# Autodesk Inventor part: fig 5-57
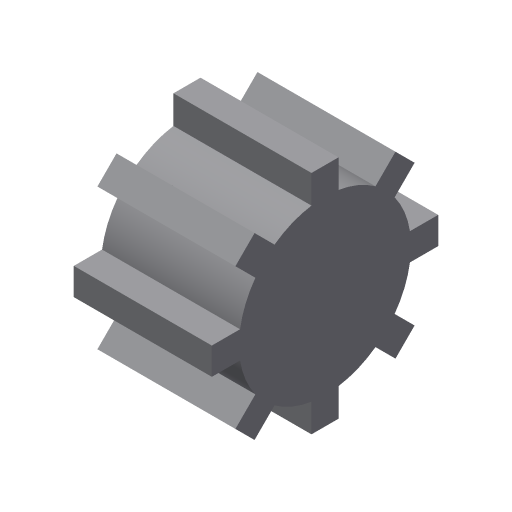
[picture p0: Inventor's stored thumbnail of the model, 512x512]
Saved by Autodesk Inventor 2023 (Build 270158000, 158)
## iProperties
Created: 2005-12
Part Number: fig 5-57
Document SubType Name: Modeling
Designer: CADCIM
Density: 1 g/cm^3
Material: Generic
Appearance: Default
Author: CADCIM
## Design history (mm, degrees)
sketch "Sketch1"
  geometry: C1 r 27.506 at (0, 0)
  constraints: 1 centre point
extrude "Extrusion1" new body sketch "Sketch1" distance "d0" = 20; taper "d1" = 0 deg
sketch "Sketch2"
  geometry: L1 (-12.302, -1.705)-(-16.396, -1.705); L2 (-16.396, -1.705)-(-16.396, 2.216); L3 (-16.396, 2.216)-(-12.302, 2.216); L4 (-7.311, -9.833)-(-10.206, -12.728); L5 (-10.206, -12.728)-(-12.979, -9.955); L6 (-12.979, -9.955)-(-10.084, -7.06); L7 (1.966, -12.051)-(1.966, -16.145); L8 (1.966, -16.145)-(-1.956, -16.145); L9 (-1.956, -16.145)-(-1.956, -12.051); L10 (10.093, -7.06)-(12.988, -9.955); L11 (12.988, -9.955)-(10.215, -12.728); L12 (10.215, -12.728)-(7.32, -9.833); L13 (12.311, 2.216)-(16.405, 2.216); L14 (16.405, 2.216)-(16.405, -1.705); L15 (16.405, -1.705)-(12.311, -1.705); L16 (7.32, 10.344)-(10.215, 13.239); L17 (10.215, 13.239)-(12.988, 10.466); L18 (12.988, 10.466)-(10.093, 7.571); L19 (-1.956, 12.562)-(-1.956, 16.656); L20 (-1.956, 16.656)-(1.966, 16.656); L21 (1.966, 16.656)-(1.966, 12.562); L22 (-10.084, 7.571)-(-12.979, 10.466); L23 (-12.979, 10.466)-(-10.206, 13.239); L24 (-10.206, 13.239)-(-7.311, 10.344); A1 r 12.462 centre (0.005, 0.256) between (-12.302, -1.705) and (-10.084, -7.06); A2 r 12.462 centre (0.005, 0.256) between (-7.311, -9.833) and (-1.956, -12.051); A3 r 12.462 centre (0.005, 0.256) between (1.966, -12.051) and (7.32, -9.833); A4 r 12.462 centre (0.005, 0.256) between (10.093, -7.06) and (12.311, -1.705); A5 r 12.462 centre (0.005, 0.256) between (12.311, 2.216) and (10.093, 7.571); A6 r 12.462 centre (0.005, 0.256) between (7.32, 10.344) and (1.966, 12.562); A7 r 12.462 centre (0.005, 0.256) between (-1.956, 12.562) and (-7.311, 10.344); A8 r 12.462 centre (0.005, 0.256) between (-10.084, 7.571) and (-12.302, 2.216)
  constraints: 48 end point, 16 point on circle, 8 centre point, 2 parallel, 1 horizontal, 1 perpendicular, 57 other
  dimensions: "d4" = 360 deg dimension on A1.centre L2.end (derived)
extrude "Extrusion2" sketch "Sketch2" distance "d6" = 20; taper "d7" = 0 deg
body "Solid1"
